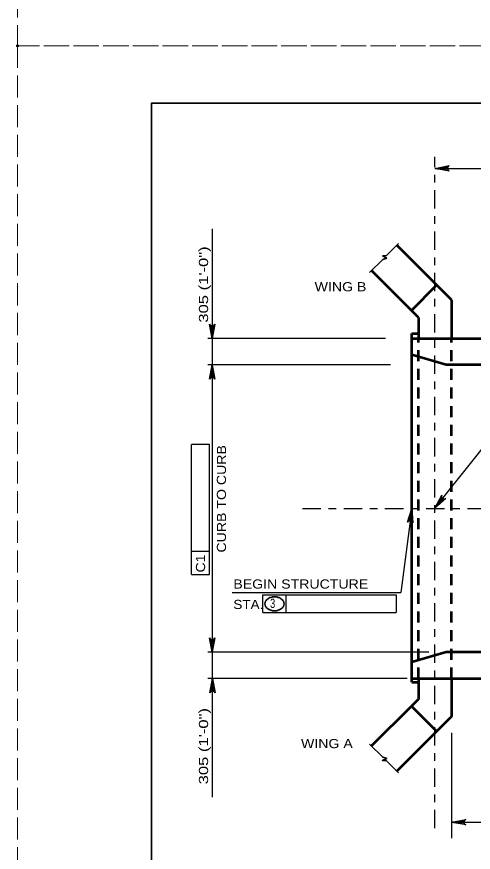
# Model space of a CAD drawing. Extents: x -11 to 79, y -154 to 0.
# Drawn here: x -0.01 to 5.96, y -32.54 to -21.62 of the extents above; entities that cross this region are included whole.
import ezdxf
from ezdxf.enums import TextEntityAlignment as Align

# ---------------------------------------------------------------- set-up
doc = ezdxf.new("R2010")
doc.units = 0
doc.header["$LTSCALE"] = 0.048
doc.header["$PDMODE"] = 32
doc.header["$PDSIZE"] = 0.024
for name, pattern in [('DOT_DASHED', [7.7, 5, -1.2, 0.3, -1.2]), ('LONG_DASHED', [7.5, 6, -1.5]), ('MEDIUM_DASHED', [4.5, 3, -1.5])]:
    doc.linetypes.add(name, pattern=pattern)
for name, color, linetype, lineweight in [('1', 7, 'Continuous', 25), ('2', 7, 'Continuous', 35), ('3', 7, 'Continuous', 25), ('4', 7, 'Continuous', 25), ('63', 7, 'LONG_DASHED', 13)]:
    doc.layers.add(name, color=color, linetype=linetype, lineweight=lineweight)
doc.layers.add('62', color=7, linetype='Continuous')

msp = doc.modelspace()

# ---------------------------------------------------------------- hatches: boundary and pattern name
at = {"layer": '4'}
for points in [[(2.52367, -25.70892), (2.56217, -25.70892), (2.54292, -25.82425)], [(2.52367, -26.28567), (2.56217, -26.28567), (2.54292, -26.17033)], [(2.52367, -29.80983), (2.56217, -29.80983), (2.54292, -29.92517)], [(2.52367, -30.38658), (2.56217, -30.38658), (2.54292, -30.27125)]]:
    msp.add_hatch(color=256, dxfattribs=at).paths.add_polyline_path(points)

# ---------------------------------------------------------------- linework, layer by layer
at = {"layer": '1', "lineweight": 35}
msp.add_lwpolyline([(1.75, -43.25), (33.25, -43.25), (33.25, -22.75), (1.75, -22.75)], close=True, dxfattribs=at)
at = {"layer": '2', "lineweight": 53}
for p, q in [((5.67208, -25.32183), (4.95742, -24.60725)), ((5.14917, -25.45742), (4.62817, -24.9365)), ((5.67208, -25.32183), (5.67208, -25.82425)), ((5.24142, -25.54967), (5.24142, -25.82425)), ((5.15625, -30.31925), (5.15625, -25.76017)), ((5.15625, -25.76017), (5.24142, -25.76017)), ((5.15625, -25.82425), (13.60442, -25.82425)), ((5.60342, -26.17025), (5.15625, -26.0395)), ((13.15733, -26.17025), (5.60342, -26.17025)), ((5.60342, -29.92517), (5.15625, -30.05583)), ((13.15733, -29.92517), (5.60342, -29.92517)), ((5.15625, -30.27117), (13.60442, -30.27117)), ((5.15625, -30.31925), (5.24142, -30.31925)), ((5.24142, -30.27117), (5.24142, -30.53867)), ((5.67208, -30.27117), (5.67208, -30.7665)), ((5.24142, -30.53867), (5.14917, -30.63092)), ((5.14917, -30.63092), (4.62825, -31.15183)), ((5.14917, -30.63092), (5.47842, -30.96017)), ((5.67208, -30.7665), (4.95742, -31.48108))]:
    msp.add_line(p, q, dxfattribs=at)
at = {"layer": '2', "linetype": 'MEDIUM_DASHED', "lineweight": 53}
for p, q in [((5.24142, -30.27117), (5.24142, -25.82425)), ((5.67208, -30.27117), (5.67208, -25.82425))]:
    msp.add_line(p, q, dxfattribs=at)
at = {"layer": '2', "lineweight": 53}
msp.add_lwpolyline([(5.24142, -25.54967), (5.14917, -25.45742), (5.47842, -25.12817)], dxfattribs=at)
at = {"layer": '3', "linetype": 'DOT_DASHED'}
msp.add_line((5.45675, -32.22608), (5.45675, -23.45242), dxfattribs=at)
at = {"layer": '3', "lineweight": 35}
for p, q in [((4.82442, -24.74025), (4.98075, -24.584)), ((4.60275, -24.96192), (4.77358, -24.79108)), ((4.82442, -24.74025), (4.77017, -24.74675)), ((4.77017, -24.74675), (4.82592, -24.77458)), ((4.82592, -24.77458), (4.77358, -24.79108)), ((4.60275, -31.12642), (4.77358, -31.29725)), ((4.82442, -31.34808), (4.98075, -31.50442))]:
    msp.add_line(p, q, dxfattribs=at)
msp.add_lwpolyline([(4.82442, -31.34808), (4.77017, -31.34158), (4.82592, -31.31375), (4.77358, -31.29725)], dxfattribs=at)
at = {"layer": '4'}
for p, q in [((5.45675, -23.60108), (13.304, -23.60108)), ((2.54292, -24.39317), (2.54292, -31.82067)), ((4.81142, -25.82433), (2.48525, -25.82425)), ((4.87742, -26.17033), (2.48525, -26.17033)), ((5.45675, -28.04325), (6.29333, -26.98983)), ((2.5095, -27.2115), (2.27325, -27.21125)), ((2.27325, -28.60958), (2.27325, -27.21125)), ((2.5095, -28.91233), (2.5095, -27.2115)), ((5.15625, -28.04767), (5.00858, -29.146)), ((2.27325, -28.91208), (2.27325, -28.60958)), ((2.5095, -28.60983), (2.27325, -28.60958)), ((2.27325, -28.91208), (2.5095, -28.91233)), ((2.80558, -29.146), (5.00858, -29.146)), ((3.20767, -29.40725), (3.20767, -29.17658)), ((3.20767, -29.17658), (3.51075, -29.17658)), ((3.51075, -29.40725), (3.51075, -29.17658)), ((3.51075, -29.17658), (4.95108, -29.17658)), ((4.95108, -29.17658), (4.95108, -29.40725)), ((3.20767, -29.40725), (4.95108, -29.40725)), ((5.37667, -29.92517), (2.48525, -29.92517)), ((5.0935, -30.27183), (2.48525, -30.27183)), ((5.67208, -30.97933), (5.67208, -32.356)), ((5.67208, -32.14992), (13.07158, -32.14992))]:
    msp.add_line(p, q, dxfattribs=at)
at = {"layer": '4', "linetype": 'DOT_DASHED'}
msp.add_line((3.72342, -28.04767), (15.124, -28.04767), dxfattribs=at)
at = {"layer": '4'}
for points in [[(5.45675, -23.60108), (5.64317, -23.56617), (5.62883, -23.57608), (5.62142, -23.58858), (5.61925, -23.60108), (5.62142, -23.61358), (5.62883, -23.62608), (5.64317, -23.636), (5.45675, -23.60108), (5.62883, -23.62608), (5.62142, -23.61358), (5.45675, -23.60108), (5.61925, -23.60108), (5.62142, -23.58858), (5.45675, -23.60108), (5.62883, -23.57608)], [(2.54292, -25.82425), (2.508, -25.63783), (2.51792, -25.65217), (2.53042, -25.65958), (2.54292, -25.66175), (2.55542, -25.65958), (2.56792, -25.65217), (2.57783, -25.63783), (2.54292, -25.82425), (2.56792, -25.65217), (2.55542, -25.65958), (2.54292, -25.82425), (2.54292, -25.66175), (2.53042, -25.65958), (2.54292, -25.82425), (2.51792, -25.65217)], [(2.54292, -26.17033), (2.57783, -26.35675), (2.56792, -26.34242), (2.55542, -26.335), (2.54292, -26.33283), (2.53042, -26.335), (2.51792, -26.34242), (2.508, -26.35675), (2.54292, -26.17033), (2.51792, -26.34242), (2.53042, -26.335), (2.54292, -26.17033), (2.54292, -26.33283), (2.55542, -26.335), (2.54292, -26.17033), (2.56792, -26.34242)], [(5.45675, -28.04325), (5.54533, -27.8755), (5.54417, -27.893), (5.54933, -27.90658), (5.55783, -27.916), (5.56892, -27.92208), (5.58333, -27.92408), (5.60008, -27.919), (5.45675, -28.04325), (5.58333, -27.92408), (5.56892, -27.92208), (5.45675, -28.04325), (5.55783, -27.916), (5.54933, -27.90658), (5.45675, -28.04325), (5.54417, -27.893)], [(5.15625, -28.04767), (5.16608, -28.23708), (5.15808, -28.2215), (5.14667, -28.2125), (5.13458, -28.20875), (5.12192, -28.20917), (5.10858, -28.21483), (5.09675, -28.22775), (5.15625, -28.04767), (5.10858, -28.21483), (5.12192, -28.20917), (5.15625, -28.04767), (5.13458, -28.20875), (5.14667, -28.2125), (5.15625, -28.04767), (5.15808, -28.2215)], [(2.54292, -29.92517), (2.508, -29.73875), (2.51792, -29.75308), (2.53042, -29.7605), (2.54292, -29.76267), (2.55542, -29.7605), (2.56792, -29.75308), (2.57783, -29.73875), (2.54292, -29.92517), (2.56792, -29.75308), (2.55542, -29.7605), (2.54292, -29.92517), (2.54292, -29.76267), (2.53042, -29.7605), (2.54292, -29.92517), (2.51792, -29.75308)], [(2.54733, -30.27183), (2.58225, -30.45825), (2.57233, -30.44392), (2.55983, -30.4365), (2.54733, -30.43433), (2.53483, -30.4365), (2.52233, -30.44392), (2.51233, -30.45825), (2.54733, -30.27183), (2.52233, -30.44392), (2.53483, -30.4365), (2.54733, -30.27183), (2.54733, -30.43433), (2.55983, -30.4365), (2.54733, -30.27183), (2.57233, -30.44392)], [(5.67208, -32.14983), (5.8585, -32.11492), (5.84417, -32.12483), (5.83675, -32.13733), (5.83458, -32.14983), (5.83675, -32.16233), (5.84417, -32.17483), (5.8585, -32.18483), (5.67208, -32.14983), (5.84417, -32.17483), (5.83675, -32.16233), (5.67208, -32.14983), (5.83458, -32.14983), (5.83675, -32.13733), (5.67208, -32.14983), (5.84417, -32.12483)]]:
    msp.add_lwpolyline(points, dxfattribs=at)
for points in [[(2.52367, -25.70892), (2.56217, -25.70892), (2.54292, -25.82425)], [(2.52367, -26.28567), (2.56217, -26.28567), (2.54292, -26.17033)], [(2.52367, -29.80983), (2.56217, -29.80983), (2.54292, -29.92517)], [(2.52367, -30.38658), (2.56217, -30.38658), (2.54292, -30.27125)]]:
    msp.add_lwpolyline(points, close=True, dxfattribs=at)
at = {"layer": '4', "lineweight": 35}
for centre, radius, start, end in [((3.30272, -29.29382), 0.06845, 150.63079, 180), ((3.32976, -29.30904), 0.09948, 126.35438, 150.63079), ((3.34742, -29.33304), 0.12928, 106.95519, 126.35438), ((3.35897, -29.37089), 0.16885, 90, 106.95519), ((3.35897, -29.37089), 0.16885, 73.04481, 90), ((3.37051, -29.33304), 0.12928, 53.64563, 73.04481), ((3.38817, -29.30904), 0.09948, 29.36921, 53.64562), ((3.41522, -29.29382), 0.06845, 0, 29.36921), ((3.30272, -29.29382), 0.06845, 180, 209.36921), ((3.32976, -29.2786), 0.09948, 209.36921, 233.64562), ((3.34742, -29.2546), 0.12928, 233.64562, 253.04481), ((3.35897, -29.21675), 0.16885, 253.04481, 270), ((3.35897, -29.21675), 0.16885, 270, 286.95519), ((3.37051, -29.2546), 0.12928, 286.95519, 306.35438), ((3.38817, -29.2786), 0.09948, 306.35438, 330.63079), ((3.41522, -29.29382), 0.06845, 330.63079, 0)]:
    msp.add_arc(centre, radius, start, end, dxfattribs=at)
at = {"layer": '62'}
msp.add_point((0, -22), dxfattribs=at)
at = {"layer": '63'}
for points in [[(0, -22), (34, -22), (34, 0), (0, 0)], [(0, -44), (34, -44), (34, -22), (0, -22)]]:
    msp.add_lwpolyline(points, close=True, dxfattribs=at)

# ---------------------------------------------------------------- texts
at = {"layer": '4'}
for s, width, p in [('305 (1\'-0")', 1.35, (2.49042, -25.61842)), ('CURB TO CURB', 1.15, (2.725, -28.62383)), ('305 (1\'-0")', 1.35, (2.49042, -31.65358))]:
    msp.add_text(s, height=0.12, rotation=90, dxfattribs=dict(at, width=width)).set_placement(p)
for s, width, p in [('WING B', 1.15, (3.88367, -25.20875)), ('BEGIN STRUCTURE', 1.15, (2.82067, -29.095)), ('STA.', 1.1, (2.82067, -29.36183)), ('3', 0.75, (3.30092, -29.34783)), ('WING A', 1.15, (3.7055, -31.1805))]:
    msp.add_text(s, height=0.12, dxfattribs=dict(at, width=width)).set_placement(p)
at = {"layer": '4', "width": 1.15}
msp.add_text('C1', height=0.12, rotation=89.938, dxfattribs=at).set_placement((2.45146, -28.7669), align=Align.CENTER)

doc.saveas('drawing.dxf')
